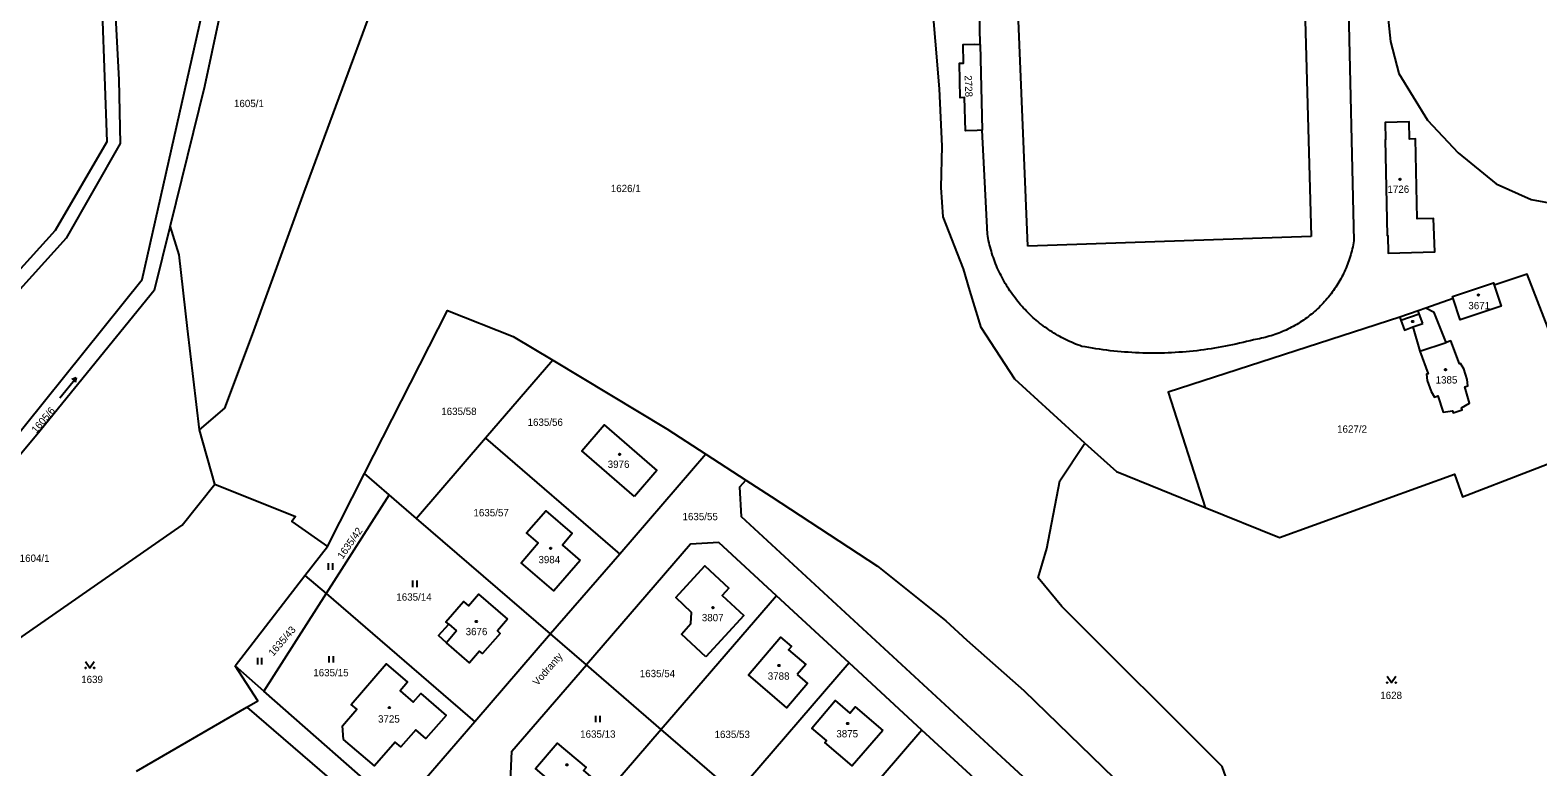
# Model space of a CAD drawing. Extents: x -679220 to -673243, y -1075091 to -1066557.
# Drawn here: x -677370.2 to -677019.6, y -1071692.7 to -1071521.5 of the extents above; entities that cross this region are included whole.
import ezdxf

# ---------------------------------------------------------------- set-up
doc = ezdxf.new("R2010")
doc.units = 0
for name, color, linetype in [('Hranice parcel', 7, 'Continuous'), ('Parcelní čísla', 7, 'Continuous'), ('Pop  PČ popisy', 7, 'Continuous'), ('Vnitřní kresba', 7, 'Continuous'), ('Značky budov', 7, 'Continuous'), ('Značky kultur', 7, 'Continuous')]:
    doc.layers.add(name, color=color, linetype=linetype)

msp = doc.modelspace()

# ---------------------------------------------------------------- linework, layer by layer
at = {"layer": 'Hranice parcel'}
for p, q in [((-677039.33, -1071583.87), (-677045.65, -1071586.08)), ((-677248.69, -1071598.22), (-677264.31, -1071616.34)), ((-677327.31, -1071627.01), (-677330.83, -1071614.4)), ((-677264.31, -1071616.34), (-677280.38, -1071634.97)), ((-677264.31, -1071616.34), (-677233.09, -1071643.26)), ((-677213.12, -1071620.01), (-677233.09, -1071643.26)), ((-677213.12, -1071620.01), (-677203.81, -1071626.06)), ((-677301.09, -1071641.5), (-677292.47, -1071624.55)), ((-677286.74, -1071629.49), (-677292.47, -1071624.55)), ((-677286.74, -1071629.49), (-677301.42, -1071652.45)), ((-677280.38, -1071634.97), (-677286.74, -1071629.49)), ((-677249.2, -1071661.84), (-677280.38, -1071634.97)), ((-677306.31, -1071648.24), (-677301.09, -1071641.5)), ((-677233.09, -1071643.26), (-677249.2, -1071661.84)), ((-677322.57, -1071669.21), (-677306.31, -1071648.24)), ((-677306.31, -1071648.24), (-677301.42, -1071652.45)), ((-677301.42, -1071652.45), (-677315.86, -1071675.12)), ((-677301.42, -1071652.45), (-677266.83, -1071682.28)), ((-677196.69, -1071652.96), (-677223.45, -1071684.02)), ((-677179.76, -1071668.57), (-677196.69, -1071652.96)), ((-677249.2, -1071661.84), (-677266.83, -1071682.28)), ((-677240.88, -1071669.01), (-677249.2, -1071661.84)), ((-677315.86, -1071675.12), (-677322.57, -1071669.21)), ((-677223.45, -1071684.02), (-677240.88, -1071669.01)), ((-677179.76, -1071668.57), (-677206.02, -1071699.04)), ((-677162.84, -1071684.18), (-677179.76, -1071668.57)), ((-677345.49, -1071693.69), (-677319.82, -1071678.84)), ((-677223.45, -1071684.02), (-677244.35, -1071708.26)), ((-677206.02, -1071699.04), (-677223.45, -1071684.02)), ((-677162.84, -1071684.18), (-677188.6, -1071714.05)), ((-677145.92, -1071699.77), (-677162.84, -1071684.18))]:
    msp.add_line(p, q, dxfattribs=at)
for points in [[(-677547.65, -1071874.9), (-677512.13, -1071839.9), (-677494.84, -1071813.59), (-677477.52, -1071787.54), (-677474.59, -1071780.52), (-677470.62, -1071763.59), (-677466.53, -1071728.98), (-677464.55, -1071710.33), (-677463.26, -1071667.2), (-677450.4, -1071640.86), (-677427.79, -1071619.2), (-677404.1, -1071607.74), (-677392.74, -1071599.33), (-677364.3, -1071568.01), (-677352.33, -1071547.38), (-677353.42, -1071517.27), (-677364.45, -1071472.8), (-677366.9, -1071460.72), (-677361.99, -1071451.74), (-677335.82, -1071408.46), (-677315.48, -1071374.36), (-677305.32, -1071362.98)], [(-677124.98, -1071617.49), (-677141.23, -1071602.64), (-677149.07, -1071590.57), (-677151.72, -1071581.97), (-677153.22, -1071577), (-677157.91, -1071564.84), (-677158.41, -1071558.04), (-677158.18, -1071548.47), (-677158.74, -1071535.15), (-677160.65, -1071512.89), (-677161.16, -1071505.19), (-677161.69, -1071497.88), (-677161.86, -1071478.06), (-677161.04, -1071446.58), (-677161.8, -1071444.85), (-677164.78, -1071441.39), (-677167.51, -1071439.85), (-677170.09, -1071439.62)], [(-677016.55, -1071448.77), (-677028.68, -1071457.97), (-677038.08, -1071466.41), (-677044.21, -1071477.45), (-677053.38, -1071497), (-677054.97, -1071503.6), (-677055.46, -1071509.26), (-677053.86, -1071524.12), (-677051.99, -1071531.58), (-677045.27, -1071542.43), (-677038.18, -1071550), (-677029.36, -1071557.24), (-677021.22, -1071560.82), (-677015.3, -1071561.94), (-677010.64, -1071561.65)], [(-677361.41, -1071471.95), (-677350.43, -1071516.86), (-677349.56, -1071533.03), (-677349.29, -1071547.83), (-677361.83, -1071569.86), (-677390.7, -1071601.66), (-677402.66, -1071610.43), (-677426.13, -1071621.73), (-677447.8, -1071642.64), (-677460.12, -1071667.74), (-677461.31, -1071710.35), (-677463.55, -1071729.64)], [(-677449.46, -1071732.84), (-677430.89, -1071685.08), (-677401.23, -1071649.29), (-677387.93, -1071633.95), (-677371.26, -1071613.2), (-677344.18, -1071579.41), (-677335.48, -1071540.9), (-677322.24, -1071482.13)], [(-677318.26, -1071483.13), (-677326.3, -1071518.6), (-677329.7, -1071534.55), (-677337.68, -1071566.95)], [(-677330.83, -1071614.4), (-677324.98, -1071609.32), (-677318.48, -1071592.22), (-677306.46, -1071559.12), (-677298.39, -1071537.17), (-677290.26, -1071515.15), (-677282.42, -1071492.25)], [(-677150.01, -1071544.78), (-677152.69, -1071544.85), (-677152.92, -1071537.15), (-677153.92, -1071537.18), (-677154.15, -1071529.19), (-677153.15, -1071529.16), (-677153.28, -1071524.84), (-677150.58, -1071524.73), (-677149.31, -1071524.78), (-677148.84, -1071544.76), (-677150.01, -1071544.78)], [(-677055.03, -1071546.96), (-677055.13, -1071546.96), (-677054.69, -1071569.25), (-677054.55, -1071569.25), (-677054.47, -1071573.29), (-677043.55, -1071573.03), (-677043.87, -1071565.24), (-677047.7, -1071565.32), (-677048.1, -1071546.76), (-677049.5, -1071546.79), (-677049.58, -1071542.83), (-677055.11, -1071542.94), (-677055.03, -1071546.96)], [(-677337.68, -1071566.95), (-677341.37, -1071581.96), (-677368.67, -1071615.55), (-677398.69, -1071651.4), (-677428.04, -1071687.44), (-677440.64, -1071720.72)], [(-677330.83, -1071614.4), (-677333.6, -1071590.82), (-677335.57, -1071573.69), (-677337.68, -1071566.95)], [(-677039.33, -1071583.87), (-677039.5, -1071583.38), (-677029.95, -1071580.18), (-677029.76, -1071580.74)], [(-677006.61, -1071618.17), (-677022.15, -1071578.23), (-677029.76, -1071580.74)], [(-677029.76, -1071580.74), (-677028.13, -1071585.63), (-677037.66, -1071588.84), (-677039.33, -1071583.87)], [(-677292.47, -1071624.55), (-677273.19, -1071586.67), (-677257.87, -1071592.72), (-677248.69, -1071598.22)], [(-677045.65, -1071586.08), (-677047.47, -1071586.72), (-677051.75, -1071588.22)], [(-677051.75, -1071588.22), (-677051.5, -1071588.88), (-677050.62, -1071591.25), (-677048.69, -1071590.47), (-677047.04, -1071596.1), (-677045.17, -1071601.36), (-677045.5, -1071601.48), (-677045.33, -1071602.92), (-677044.43, -1071605.51), (-677043.68, -1071606.76), (-677042.91, -1071606.5), (-677041.65, -1071610.27), (-677039.46, -1071609.99), (-677039.3, -1071610.46), (-677037.26, -1071609.76), (-677037.41, -1071609.3), (-677035.51, -1071608.18), (-677036.62, -1071604.37), (-677035.94, -1071604.16), (-677036.06, -1071602.72), (-677036.83, -1071600.17), (-677037.62, -1071598.94), (-677037.86, -1071599.01), (-677039.85, -1071593.69), (-677040.97, -1071594.07), (-677043.7, -1071587.13), (-677045.65, -1071586.08)], [(-677051.75, -1071588.22), (-677105.63, -1071605.66), (-677096.97, -1071632.46)], [(-677248.69, -1071598.22), (-677222.15, -1071614.13), (-677213.12, -1071620.01)], [(-677229.7, -1071629.87), (-677241.96, -1071619.28), (-677236.72, -1071613.2), (-677224.46, -1071623.81), (-677229.7, -1071629.87)], [(-677072.54, -1071729.05), (-677086.59, -1071710.67), (-677093.03, -1071692.61), (-677130.34, -1071655.44), (-677135.83, -1071648.8), (-677133.83, -1071641.99), (-677130.78, -1071626.26), (-677124.98, -1071617.49)], [(-677124.98, -1071617.49), (-677117.62, -1071624.07), (-677096.97, -1071632.46)], [(-677096.97, -1071632.46), (-677079.7, -1071639.42), (-677039, -1071624.72), (-677037.17, -1071629.98), (-677006.61, -1071618.17)], [(-677203.81, -1071626.06), (-677205.28, -1071627.7), (-677204.89, -1071634.52), (-677143.42, -1071691.21), (-677025.94, -1071799.59)], [(-677203.81, -1071626.06), (-677197.92, -1071629.89), (-677173.19, -1071646.04), (-677157.32, -1071658.82), (-677152.38, -1071663.28), (-677139.17, -1071675), (-677112.89, -1071700.45), (-677099.77, -1071713.06), (-677078.77, -1071736.63)], [(-677422.65, -1071724.8), (-677405.05, -1071685.3), (-677334.85, -1071636.58), (-677327.31, -1071627.01)], [(-677327.31, -1071627.01), (-677308.55, -1071634.5), (-677309.36, -1071635.71), (-677301.09, -1071641.5)], [(-677242.3, -1071644.72), (-677248.45, -1071651.83), (-677256.06, -1071645.3), (-677252.06, -1071640.65), (-677254.77, -1071638.32), (-677250.28, -1071633.23), (-677244.16, -1071638.5), (-677246.41, -1071641.16), (-677242.3, -1071644.72)], [(-677196.69, -1071652.96), (-677210.11, -1071640.57), (-677216.7, -1071640.96), (-677240.88, -1071669.01)], [(-677213.09, -1071667.15), (-677218.79, -1071661.92), (-677216.55, -1071659.44), (-677216.46, -1071656.81), (-677220.1, -1071653.37), (-677213.33, -1071646.03), (-677207.74, -1071651.16), (-677209.31, -1071652.91), (-677204.24, -1071657.53), (-677213.09, -1071667.15)], [(-677259.25, -1071658.4), (-677261.57, -1071661.11), (-677260.94, -1071661.7), (-677265.03, -1071666.39), (-677265.71, -1071665.81), (-677268.08, -1071668.51), (-677273.41, -1071663.87), (-677275.29, -1071662.23), (-677272.85, -1071659.58), (-677273.52, -1071658.99), (-677269.47, -1071654.29), (-677268.32, -1071655.27), (-677265.96, -1071652.59), (-677259.25, -1071658.4)], [(-677191.84, -1071671.27), (-677189.42, -1071673.32), (-677194.24, -1071678.99), (-677203.19, -1071671.36), (-677195.7, -1071662.58), (-677193.19, -1071664.72), (-677193.85, -1071665.5), (-677189.87, -1071668.92), (-677191.84, -1071671.27)], [(-677319.82, -1071678.84), (-677317.25, -1071677.35), (-677322.57, -1071669.21)], [(-677297.34, -1071686.35), (-677297.6, -1071683.22), (-677294.29, -1071679.35), (-677295.56, -1071678.22), (-677287.43, -1071668.76), (-677282.5, -1071673.02), (-677284.19, -1071675.02), (-677281.12, -1071677.68), (-677279.37, -1071675.68), (-677273.51, -1071680.76), (-677278.18, -1071686.13), (-677280.54, -1071684.09), (-677284.01, -1071688.05), (-677285.31, -1071687.01), (-677290.16, -1071692.5), (-677297.34, -1071686.35)], [(-677244.35, -1071708.26), (-677258.52, -1071696.05), (-677258.18, -1071689.08), (-677240.88, -1071669.01)], [(-677266.83, -1071682.28), (-677284.46, -1071702.73), (-677315.86, -1071675.12)], [(-677171.97, -1071684.28), (-677179.08, -1071692.52), (-677185.44, -1071687.09), (-677185.05, -1071686.63), (-677188.46, -1071683.71), (-677183.01, -1071677.33), (-677179.62, -1071680.25), (-677178.38, -1071678.81), (-677171.97, -1071684.28)], [(-677319.82, -1071678.84), (-677287.72, -1071706.52), (-677302.09, -1071723.18)], [(-677238.93, -1071695.79), (-677242.82, -1071700.37), (-677245.42, -1071698.16), (-677245.99, -1071698.84), (-677252.68, -1071693.14), (-677247.63, -1071687.2), (-677240.93, -1071692.89), (-677241.53, -1071693.58), (-677238.93, -1071695.79)]]:
    msp.add_lwpolyline(points, dxfattribs=at)
at = {"layer": 'Vnitřní kresba'}
for p, q in [((-677149.31, -1071524.78), (-677150.59, -1071462.19)), ((-677064.97, -1071462.71), (-677062.4, -1071570.47)), ((-677075.12, -1071467.41), (-677072.33, -1071569.42)), ((-677138.26, -1071571.7), (-677142.43, -1071469.97)), ((-677147.63, -1071568.88), (-677148.84, -1071544.76)), ((-677072.33, -1071569.42), (-677138.26, -1071571.7)), ((-677051.5, -1071588.88), (-677047.21, -1071587.4)), ((-677047.21, -1071587.4), (-677047.47, -1071586.72)), ((-677046.37, -1071589.64), (-677047.21, -1071587.4)), ((-677048.69, -1071590.47), (-677046.37, -1071589.64)), ((-677047.04, -1071596.1), (-677040.97, -1071594.07)), ((-677271.07, -1071661.14), (-677273.41, -1071663.87)), ((-677272.85, -1071659.58), (-677271.07, -1071661.14))]:
    msp.add_line(p, q, dxfattribs=at)
for points in [[(-677125.69, -1071594.98), (-677126.17, -1071594.81), (-677126.65, -1071594.63), (-677127.12, -1071594.44), (-677127.6, -1071594.24), (-677128.07, -1071594.04), (-677128.53, -1071593.83), (-677128.99, -1071593.62), (-677129.46, -1071593.39), (-677129.91, -1071593.16), (-677130.36, -1071592.93), (-677130.81, -1071592.68), (-677131.26, -1071592.43), (-677131.7, -1071592.17), (-677132.14, -1071591.91), (-677132.57, -1071591.64), (-677133, -1071591.36), (-677133.42, -1071591.07), (-677133.84, -1071590.78), (-677134.26, -1071590.49), (-677134.67, -1071590.18), (-677135.08, -1071589.87), (-677135.48, -1071589.56), (-677135.88, -1071589.24), (-677136.27, -1071588.91), (-677136.66, -1071588.57), (-677137.04, -1071588.24), (-677137.41, -1071587.89), (-677137.78, -1071587.54), (-677138.15, -1071587.18), (-677138.51, -1071586.82), (-677138.86, -1071586.45), (-677139.22, -1071586.08), (-677139.56, -1071585.7), (-677139.9, -1071585.32), (-677140.23, -1071584.93), (-677140.55, -1071584.54), (-677140.87, -1071584.14), (-677141.19, -1071583.73), (-677141.49, -1071583.32), (-677141.8, -1071582.91), (-677142.09, -1071582.5), (-677142.38, -1071582.07), (-677142.66, -1071581.65), (-677142.94, -1071581.22), (-677143.21, -1071580.78), (-677143.47, -1071580.34), (-677143.72, -1071579.9), (-677143.97, -1071579.46), (-677144.21, -1071579.01), (-677144.45, -1071578.55), (-677144.68, -1071578.09), (-677144.9, -1071577.63), (-677145.11, -1071577.17), (-677145.32, -1071576.7), (-677145.52, -1071576.23), (-677145.71, -1071575.76), (-677145.9, -1071575.28), (-677146.08, -1071574.8), (-677146.24, -1071574.32), (-677146.41, -1071573.84), (-677146.57, -1071573.35), (-677146.71, -1071572.86), (-677146.85, -1071572.37), (-677146.99, -1071571.88), (-677147.11, -1071571.38), (-677147.23, -1071570.89), (-677147.34, -1071570.39), (-677147.45, -1071569.89), (-677147.54, -1071569.38), (-677147.63, -1071568.88)], [(-677062.4, -1071570.47), (-677062.48, -1071570.93), (-677062.57, -1071571.39), (-677062.67, -1071571.84), (-677062.77, -1071572.3), (-677062.88, -1071572.75), (-677063, -1071573.21), (-677063.12, -1071573.66), (-677063.26, -1071574.1), (-677063.4, -1071574.55), (-677063.55, -1071574.99), (-677063.71, -1071575.43), (-677063.87, -1071575.87), (-677064.04, -1071576.3), (-677064.22, -1071576.73), (-677064.4, -1071577.16), (-677064.6, -1071577.59), (-677064.8, -1071578.01), (-677065, -1071578.43), (-677065.22, -1071578.84), (-677065.44, -1071579.26), (-677065.66, -1071579.66), (-677065.9, -1071580.07), (-677066.14, -1071580.47), (-677066.39, -1071580.86), (-677066.64, -1071581.25), (-677066.9, -1071581.64), (-677067.17, -1071582.02), (-677067.44, -1071582.4), (-677067.72, -1071582.78), (-677068.01, -1071583.15), (-677068.3, -1071583.51), (-677068.6, -1071583.87), (-677068.9, -1071584.22), (-677069.21, -1071584.57), (-677069.53, -1071584.92), (-677069.85, -1071585.25), (-677070.18, -1071585.59), (-677070.51, -1071585.92), (-677070.85, -1071586.24), (-677071.19, -1071586.55), (-677071.54, -1071586.86), (-677071.9, -1071587.17), (-677072.25, -1071587.47), (-677072.62, -1071587.76), (-677072.99, -1071588.05), (-677073.36, -1071588.32), (-677073.74, -1071588.6), (-677074.12, -1071588.87), (-677074.51, -1071589.13), (-677074.9, -1071589.38), (-677075.3, -1071589.63), (-677075.7, -1071589.87), (-677076.1, -1071590.1), (-677076.51, -1071590.33), (-677076.92, -1071590.55), (-677077.33, -1071590.77), (-677077.75, -1071590.98), (-677078.17, -1071591.18), (-677078.6, -1071591.37), (-677079.03, -1071591.55), (-677079.46, -1071591.73), (-677079.89, -1071591.9), (-677080.33, -1071592.07), (-677080.77, -1071592.22), (-677081.21, -1071592.37), (-677081.66, -1071592.51), (-677082.1, -1071592.65), (-677082.55, -1071592.78), (-677083.01, -1071592.9), (-677083.46, -1071593.01), (-677083.91, -1071593.11), (-677084.37, -1071593.21), (-677084.83, -1071593.3), (-677085.29, -1071593.38), (-677085.75, -1071593.45)], [(-677085.75, -1071593.45), (-677086.56, -1071593.67), (-677087.38, -1071593.88), (-677088.19, -1071594.08), (-677089.01, -1071594.27), (-677089.83, -1071594.46), (-677090.65, -1071594.64), (-677091.47, -1071594.81), (-677092.29, -1071594.97), (-677093.12, -1071595.12), (-677093.95, -1071595.27), (-677094.78, -1071595.41), (-677095.6, -1071595.54), (-677096.44, -1071595.67), (-677097.27, -1071595.78), (-677098.1, -1071595.89), (-677098.93, -1071595.99), (-677099.77, -1071596.08), (-677100.6, -1071596.16), (-677101.44, -1071596.24), (-677102.28, -1071596.31), (-677103.12, -1071596.37), (-677103.96, -1071596.42), (-677104.79, -1071596.46), (-677105.63, -1071596.5), (-677106.47, -1071596.53), (-677107.31, -1071596.55), (-677108.15, -1071596.56), (-677108.99, -1071596.56), (-677109.83, -1071596.56), (-677110.67, -1071596.55), (-677111.51, -1071596.53), (-677112.35, -1071596.5), (-677113.19, -1071596.47), (-677114.03, -1071596.42), (-677114.87, -1071596.37), (-677115.71, -1071596.31), (-677116.54, -1071596.24), (-677117.38, -1071596.17), (-677118.21, -1071596.08), (-677119.05, -1071595.99), (-677119.88, -1071595.9), (-677120.72, -1071595.79), (-677121.55, -1071595.67), (-677122.38, -1071595.55), (-677123.21, -1071595.42), (-677124.04, -1071595.28), (-677124.86, -1071595.13), (-677125.69, -1071594.98)]]:
    msp.add_lwpolyline(points, dxfattribs=at)
at = {"layer": 'Značky budov'}
for centre in [(-677051.68, -1071556.16), (-677033.44, -1071583.05), (-677048.75, -1071589.2), (-677041.11, -1071600.41), (-677233.16, -1071620.07), (-677249.17, -1071641.95), (-677211.46, -1071655.74), (-677266.45, -1071658.94), (-677196.08, -1071669.16), (-677286.69, -1071678.94), (-677180.12, -1071682.64), (-677245.41, -1071692.26)]:
    msp.add_circle(centre, 0.175, dxfattribs=at)
at = {"layer": 'Značky kultur'}
for p, q in [((-677363.32, -1071606.94), (-677359.55, -1071602.28)), ((-677359.55, -1071602.28), (-677360.55, -1071602.72)), ((-677359.55, -1071602.28), (-677359.77, -1071603.36)), ((-677300.84, -1071646.9), (-677300.84, -1071645.4)), ((-677299.84, -1071646.9), (-677299.84, -1071645.4)), ((-677281.26, -1071650.94), (-677281.26, -1071649.44)), ((-677280.26, -1071650.94), (-677280.26, -1071649.44)), ((-677317.31, -1071668.92), (-677317.31, -1071667.42)), ((-677316.31, -1071668.92), (-677316.31, -1071667.42)), ((-677300.71, -1071668.48), (-677300.71, -1071666.98)), ((-677299.71, -1071668.48), (-677299.71, -1071666.98)), ((-677238.66, -1071682.34), (-677238.66, -1071680.84)), ((-677237.66, -1071682.34), (-677237.66, -1071680.84))]:
    msp.add_line(p, q, dxfattribs=at)
for points in [[(-677357.31, -1071668.23), (-677356.31, -1071669.73), (-677355.31, -1071668.23)], [(-677054.67, -1071671.65), (-677053.67, -1071673.15), (-677052.67, -1071671.65)]]:
    msp.add_lwpolyline(points, dxfattribs=at)
for centre in [(-677357.31, -1071669.73), (-677355.31, -1071669.73), (-677054.67, -1071673.15), (-677052.67, -1071673.15)]:
    msp.add_circle(centre, 0.1, dxfattribs=at)

# ---------------------------------------------------------------- texts
at = {"layer": 'Parcelní čísla'}
for s, rotation, p in [('2728', 272, (-677152.93, -1071532.01)), ('1605/6', 50, (-677368.77, -1071615.32)), ('1635/42', 55, (-677297.54, -1071644.57)), ('1635/43', 49, (-677313.7, -1071667.14))]:
    msp.add_text(s, height=1.7, rotation=rotation, dxfattribs=at).set_placement(p)
for s, p in [('1605/1', (-677322.82, -1071539.37)), ('1626/1', (-677235.2, -1071559.13)), ('1726', (-677054.6, -1071559.3)), ('3671', (-677035.79, -1071586.35)), ('1385', (-677043.4, -1071603.62)), ('1635/58', (-677274.62, -1071610.94)), ('1635/56', (-677254.55, -1071613.46)), ('1627/2', (-677066.31, -1071615.05)), ('3976', (-677235.92, -1071623.23)), ('1635/57', (-677267.13, -1071634.49)), ('1635/55', (-677218.52, -1071635.39)), ('1604/1', (-677372.65, -1071645.07)), ('3984', (-677252.02, -1071645.39)), ('1635/14', (-677285.07, -1071654.09)), ('3807', (-677214.03, -1071658.88)), ('3676', (-677268.95, -1071662.12)), ('1639', (-677358.35, -1071673.25)), ('1635/15', (-677304.38, -1071671.67)), ('1635/54', (-677228.46, -1071671.88)), ('3788', (-677198.7, -1071672.46)), ('1628', (-677056.27, -1071676.95)), ('3725', (-677289.32, -1071682.43)), ('1635/13', (-677242.32, -1071685.95)), ('1635/53', (-677211.07, -1071686.02)), ('3875', (-677182.75, -1071685.88))]:
    msp.add_text(s, height=1.7, dxfattribs=at).set_placement(p)
at = {"layer": 'Pop  PČ popisy'}
msp.add_text('Vodranty', height=1.7, rotation=49, dxfattribs=at).set_placement((-677252.24, -1071673.98))

doc.saveas('drawing.dxf')
